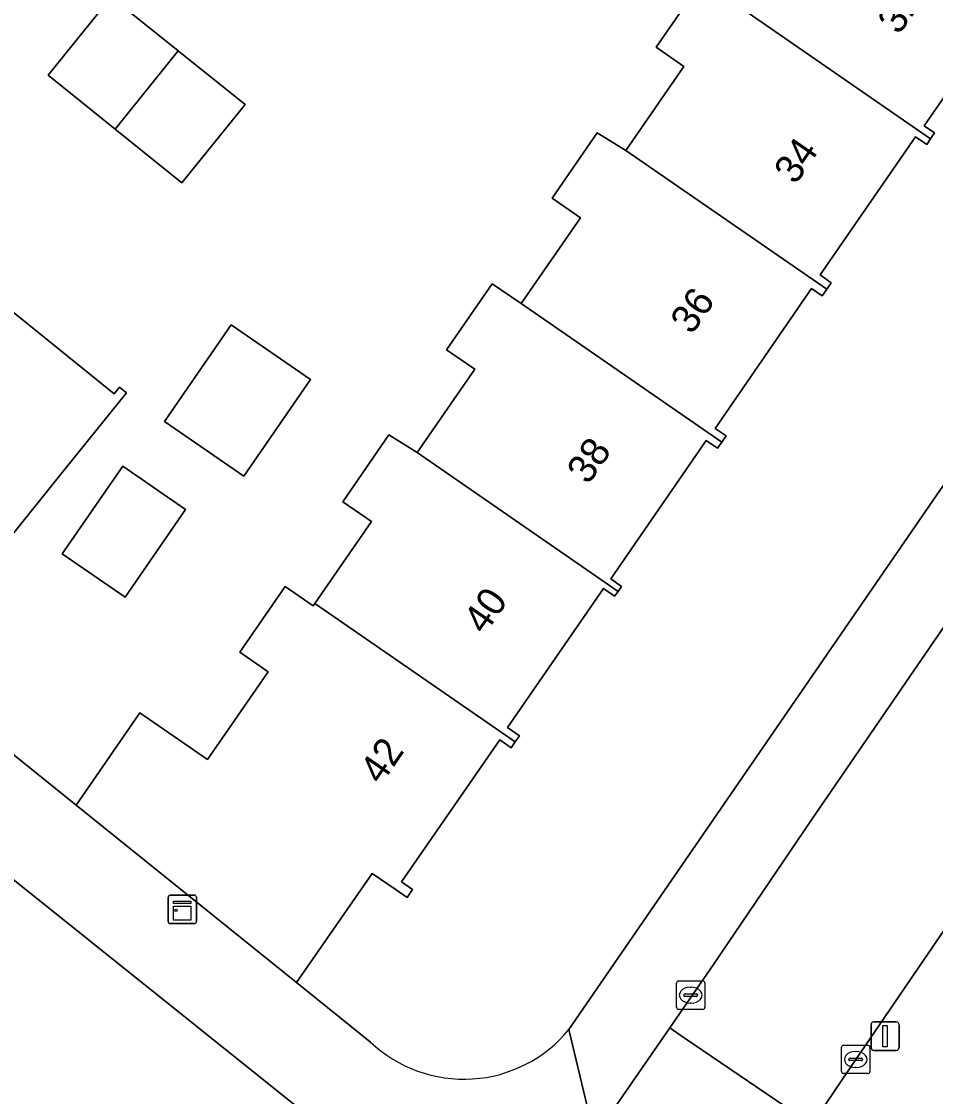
# Model space of a CAD drawing. Extents: x 160157 to 160921, y 381516 to 382045.
# Drawn here: x 160586.64 to 160618.81, y 381685.82 to 381723.64 of the extents above; entities that cross this region are included whole.
import ezdxf

# ---------------------------------------------------------------- set-up
doc = ezdxf.new("R2010")
doc.units = 0
for name, color, linetype in [('IMGEO_Erf', 7, 'Continuous'), ('IMGEO_Kast', 7, 'Continuous'), ('IMGEO_Kolk', 7, 'Continuous'), ('IMGEO_Lichtmast', 7, 'Continuous'), ('IMGEO_Pand', 7, 'Continuous'), ('IMGEO_Pand_nummerreeks', 7, 'Continuous'), ('IMGEO_Rijbaan_lokaal_open', 7, 'Continuous'), ('IMGEO_Voetpad_open', 7, 'Continuous')]:
    doc.layers.add(name, color=color, linetype=linetype)

msp = doc.modelspace()

# ---------------------------------------------------------------- linework, layer by layer
at = {"layer": 'IMGEO_Erf'}
for points in [[(160605.905, 381688.17), (160640.592, 381738.561)], [(160608.978, 381722.731), (160610.55, 381725.008)], [(160621.759, 381724.825), (160618.405, 381719.969), (160618.774, 381719.715), (160618.634, 381719.512), (160618.496, 381719.312), (160618.104, 381719.583), (160614.745, 381714.72), (160615.138, 381714.448), (160614.979, 381714.217), (160614.817, 381713.983), (160614.445, 381714.24), (160611.047, 381709.322), (160611.433, 381709.056), (160611.283, 381708.839), (160611.133, 381708.621), (160610.736, 381708.894), (160607.375, 381704.027), (160607.755, 381703.764), (160607.635, 381703.589), (160607.514, 381703.414), (160607.123, 381703.685), (160603.744, 381698.793), (160604.161, 381698.505), (160604.016, 381698.295), (160603.87, 381698.084), (160603.467, 381698.363), (160600.014, 381693.364), (160600.403, 381693.096), (160600.209, 381692.815), (160599.82, 381693.084), (160598.975, 381693.667), (160596.32, 381689.825), (160598.92, 381687.732)], [(160578.193, 381704.418), (160588.56, 381696.072), (160590.799, 381699.315), (160593.183, 381697.668), (160595.32, 381700.762), (160594.323, 381701.451), (160595.918, 381703.761), (160596.908, 381703.077), (160596.966, 381703.161), (160598.956, 381706.042), (160597.946, 381706.74), (160599.571, 381709.092), (160600.567, 381708.468), (160602.593, 381711.402), (160601.601, 381712.087), (160603.199, 381714.402), (160604.225, 381713.711), (160606.31, 381716.73), (160605.312, 381717.419), (160606.899, 381719.717), (160607.906, 381719.099), (160609.95, 381722.059), (160608.978, 381722.731)], [(160585.535, 381714.051), (160589.893, 381710.543), (160590.081, 381710.777), (160590.328, 381710.577), (160587.927, 381707.594), (160584.791, 381703.699)]]:
    msp.add_lwpolyline(points, dxfattribs=at)
for points in [[(160592.15, 381722.608), (160594.504, 381720.713), (160592.285, 381717.957), (160589.931, 381719.852), (160587.578, 381721.747), (160589.796, 381724.503)], [(160591.675, 381709.568), (160594.022, 381712.965), (160596.807, 381711.041), (160594.46, 381707.643)], [(160590.28, 381703.382), (160588.07, 381704.909), (160590.201, 381707.994), (160592.411, 381706.467)]]:
    msp.add_lwpolyline(points, close=True, dxfattribs=at)
msp.add_arc((160602.208, 381691.213), 4.788, 226.6311, 320.5451, dxfattribs=at)
at = {"layer": 'IMGEO_Kast'}
for p, q in [((160591.872, 381692.9), (160592.713, 381692.9)), ((160592.713, 381692.9), (160591.872, 381692.9)), ((160591.797, 381691.975), (160591.797, 381692.816)), ((160591.797, 381692.816), (160591.797, 381691.975)), ((160592.797, 381692.825), (160592.797, 381691.984)), ((160592.797, 381691.984), (160592.797, 381692.825)), ((160592.722, 381691.9), (160591.881, 381691.9)), ((160591.881, 381691.9), (160592.722, 381691.9))]:
    msp.add_line(p, q, dxfattribs=at)
for points in [[(160591.992, 381692.69), (160592.592, 381692.69), (160592.592, 381692.605), (160591.992, 381692.605), (160591.992, 381692.69)], [(160591.992, 381692.515), (160592.592, 381692.515), (160592.592, 381692.026), (160591.992, 381692.026), (160591.992, 381692.515)]]:
    msp.add_lwpolyline(points, dxfattribs=at)
msp.add_circle((160592.076, 381692.364), 0.0377, dxfattribs=at)
for centre, start, end in [((160591.875, 381692.822), 92.4484, 184.2845), ((160591.875, 381692.822), 92.4484, 184.2845), ((160592.719, 381692.822), 2.4484, 94.2845), ((160592.719, 381692.822), 2.4484, 94.2845), ((160591.875, 381691.978), 182.4484, 274.2845), ((160591.875, 381691.978), 182.4484, 274.2845), ((160592.719, 381691.978), 272.4484, 4.2845), ((160592.719, 381691.978), 272.4484, 4.2845)]:
    msp.add_arc(centre, 0.0779, start, end, dxfattribs=at)
at = {"layer": 'IMGEO_Kolk'}
for p, q in [((160609.69, 381688.957), (160609.69, 381689.809)), ((160609.765, 381689.883), (160610.617, 381689.883)), ((160610.691, 381689.809), (160610.691, 381688.957)), ((160609.992, 381689.426), (160610.39, 381689.426)), ((160610.178, 381689.663), (160610.203, 381689.663)), ((160609.949, 381689.377), (160609.949, 381689.389)), ((160610.387, 381689.34), (160609.989, 381689.34)), ((160610.201, 381689.103), (160610.176, 381689.103)), ((160610.433, 381689.389), (160610.433, 381689.377)), ((160610.617, 381688.883), (160609.765, 381688.883)), ((160615.498, 381686.695), (160615.498, 381687.547)), ((160615.573, 381687.621), (160616.425, 381687.621)), ((160616.499, 381687.547), (160616.499, 381686.695)), ((160615.8, 381687.164), (160616.198, 381687.164)), ((160615.986, 381687.401), (160616.011, 381687.401)), ((160615.757, 381687.115), (160615.757, 381687.127)), ((160616.195, 381687.078), (160615.797, 381687.078)), ((160616.009, 381686.841), (160615.984, 381686.841)), ((160616.241, 381687.127), (160616.241, 381687.115)), ((160616.425, 381686.621), (160615.573, 381686.621))]:
    msp.add_line(p, q, dxfattribs=at)
for points in [[(160609.69, 381688.957), (160609.69, 381689.809)], [(160609.765, 381689.883), (160610.617, 381689.883)], [(160610.691, 381689.809), (160610.691, 381688.957)], [(160610.617, 381688.883), (160609.765, 381688.883)], [(160615.498, 381686.695), (160615.498, 381687.547)], [(160615.573, 381687.621), (160616.425, 381687.621)], [(160616.499, 381687.547), (160616.499, 381686.695)], [(160616.425, 381686.621), (160615.573, 381686.621)]]:
    msp.add_lwpolyline(points, dxfattribs=at)
for centre, radius, start, end in [((160609.767, 381689.807), 0.0765, 91.552, 178.448), ((160609.767, 381689.807), 0.0765, 91.552, 178.448), ((160610.615, 381689.807), 0.0765, 1.552, 88.448), ((160610.615, 381689.807), 0.0765, 1.552, 88.448), ((160609.989, 381689.386), 0.0403, 85.8775, 175.7526), ((160610.394, 381689.388), 0.0386, 1.7309, 96.639), ((160609.986, 381689.376), 0.0366, 178.938, 274.7102), ((160610.39, 381689.383), 0.043, 264.8664, 352.4533), ((160609.767, 381688.959), 0.0765, 181.552, 268.448), ((160609.767, 381688.959), 0.0765, 181.552, 268.448), ((160610.615, 381688.959), 0.0765, 271.552, 358.448), ((160610.615, 381688.959), 0.0765, 271.552, 358.448), ((160615.575, 381687.545), 0.0765, 91.552, 178.448), ((160615.575, 381687.545), 0.0765, 91.552, 178.448), ((160616.423, 381687.545), 0.0765, 1.552, 88.448), ((160616.423, 381687.545), 0.0765, 1.552, 88.448), ((160615.797, 381687.124), 0.0403, 85.8775, 175.7526), ((160616.202, 381687.126), 0.0386, 1.7309, 96.639), ((160615.794, 381687.114), 0.0366, 178.938, 274.7102), ((160616.198, 381687.121), 0.043, 264.8664, 352.4533), ((160615.575, 381686.697), 0.0765, 181.552, 268.448), ((160615.575, 381686.697), 0.0765, 181.552, 268.448), ((160616.423, 381686.697), 0.0765, 271.552, 358.448), ((160616.423, 381686.697), 0.0765, 271.552, 358.448)]:
    msp.add_arc(centre, radius, start, end, dxfattribs=at)
for centre, major_axis, ratio, start_param, end_param in [((160610.177, 381689.383), (-0.387, 0.002), 0.722429, 4.712389, 7.853982), ((160610.202, 381689.383), (-0.39, 0.002), 0.717154, 1.570796, 4.712389), ((160615.985, 381687.121), (-0.387, 0.002), 0.722429, 4.712389, 7.853982), ((160616.01, 381687.121), (-0.39, 0.002), 0.717154, 1.570796, 4.712389)]:
    msp.add_ellipse(centre, major_axis=major_axis, ratio=ratio, start_param=start_param, end_param=end_param, dxfattribs=at)
at = {"layer": 'IMGEO_Lichtmast'}
for p, q in [((160616.537, 381687.541), (160616.537, 381688.341)), ((160616.537, 381688.341), (160616.537, 381687.541)), ((160616.637, 381688.441), (160617.427, 381688.441)), ((160617.427, 381688.441), (160616.637, 381688.441)), ((160617.527, 381688.341), (160617.527, 381687.541)), ((160617.527, 381687.541), (160617.527, 381688.341)), ((160617.427, 381687.441), (160616.637, 381687.441)), ((160616.637, 381687.441), (160617.427, 381687.441))]:
    msp.add_line(p, q, dxfattribs=at)
msp.add_lwpolyline([(160616.957, 381688.316), (160617.107, 381688.316), (160617.107, 381687.566), (160616.957, 381687.566), (160616.957, 381688.316)], dxfattribs=at)
for centre, start, end in [((160616.637, 381688.341), 90, 180), ((160616.637, 381688.341), 90, 180), ((160617.427, 381688.341), 0, 90), ((160617.427, 381688.341), 360, 90), ((160616.637, 381687.541), 180, 270), ((160616.637, 381687.541), 180, 270), ((160617.427, 381687.541), 270, 0), ((160617.427, 381687.541), 270, 0)]:
    msp.add_arc(centre, 0.1, start, end, dxfattribs=at)
at = {"layer": 'IMGEO_Pand'}
for points in [[(160618.634, 381719.512), (160618.774, 381719.715), (160618.405, 381719.969), (160621.759, 381724.825), (160622.167, 381724.544), (160622.316, 381724.76), (160614.228, 381730.33), (160612.619, 381728), (160613.595, 381727.326), (160611.566, 381724.39)], [(160618.634, 381719.512), (160611.566, 381724.39), (160610.55, 381725.008), (160608.978, 381722.731), (160609.95, 381722.059), (160607.906, 381719.099), (160614.979, 381714.217), (160615.138, 381714.448), (160614.745, 381714.72), (160618.104, 381719.583), (160618.496, 381719.312)], [(160592.15, 381722.608), (160589.796, 381724.503), (160587.578, 381721.747), (160589.931, 381719.852)], [(160592.15, 381722.608), (160589.931, 381719.852), (160592.285, 381717.957), (160594.504, 381720.713)], [(160604.225, 381713.711), (160611.283, 381708.839), (160611.433, 381709.056), (160611.047, 381709.322), (160614.445, 381714.24), (160614.817, 381713.983), (160614.979, 381714.217), (160607.906, 381719.099), (160606.899, 381719.717), (160605.312, 381717.419), (160606.31, 381716.73)], [(160585.548, 381714.52), (160579.982, 381707.608), (160580.186, 381707.444), (160580.444, 381707.765), (160584.753, 381704.296), (160584.477, 381703.952), (160584.791, 381703.699), (160587.927, 381707.594), (160590.328, 381710.577), (160590.081, 381710.777), (160589.893, 381710.543), (160585.535, 381714.051), (160585.769, 381714.342)], [(160604.225, 381713.711), (160603.199, 381714.402), (160601.601, 381712.087), (160602.593, 381711.402), (160600.567, 381708.468), (160607.635, 381703.589), (160607.755, 381703.764), (160607.375, 381704.027), (160610.736, 381708.894), (160611.133, 381708.621), (160611.283, 381708.839)], [(160591.675, 381709.568), (160594.46, 381707.643), (160596.807, 381711.041), (160594.022, 381712.965)], [(160604.016, 381698.295), (160604.161, 381698.505), (160603.744, 381698.793), (160607.123, 381703.685), (160607.514, 381703.414), (160607.635, 381703.589), (160600.567, 381708.468), (160599.571, 381709.092), (160597.946, 381706.74), (160598.956, 381706.042), (160596.966, 381703.161)], [(160590.28, 381703.382), (160592.411, 381706.467), (160590.201, 381707.994), (160588.07, 381704.909)], [(160604.016, 381698.295), (160596.966, 381703.161), (160596.908, 381703.077), (160595.918, 381703.761), (160594.323, 381701.451), (160595.32, 381700.762), (160593.183, 381697.668), (160590.799, 381699.315), (160588.56, 381696.072), (160596.32, 381689.825), (160598.975, 381693.667), (160599.82, 381693.084), (160600.209, 381692.815), (160600.403, 381693.096), (160600.014, 381693.364), (160603.467, 381698.363), (160603.87, 381698.084)]]:
    msp.add_lwpolyline(points, close=True, dxfattribs=at)
at = {"layer": 'IMGEO_Rijbaan_lokaal_open'}
for points in [[(160678.334, 381788.56), (160651.806, 381750), (160643.136, 381737.367), (160641.13, 381734.448), (160614.441, 381695.549), (160610.996, 381690.462), (160609.452, 381688.229), (160609.962, 381687.883), (160614.454, 381684.835), (160615.999, 381687.121), (160619.05, 381691.582), (160640.187, 381722.521), (160642.496, 381725.9), (160658.96, 381750), (160667.503, 381762.414)], [(160614.454, 381684.835), (160609.962, 381687.883), (160609.452, 381688.229), (160606.806, 381684.4)]]:
    msp.add_lwpolyline(points, dxfattribs=at)
msp.add_lwpolyline([(160568.758, 381707.591), (160557.554, 381716.59), (160557.502, 381716.634), (160557.472, 381716.661), (160550.945, 381722.011), (160550.931, 381722.022), (160550.918, 381722.034), (160550.145, 381722.678), (160546.247, 381717.93), (160547.02, 381717.298), (160547.066, 381717.257), (160553.47, 381712.091), (160558.948, 381707.655), (160565.145, 381702.637), (160577.959, 381692.258), (160593.928, 381679.339), (160594.486, 381678.894), (160598.404, 381683.766), (160597.642, 381684.404), (160592.745, 381688.322), (160581.553, 381697.274)], close=True, dxfattribs=at)
at = {"layer": 'IMGEO_Voetpad_open'}
msp.add_lwpolyline([(160707.501, 381830.956), (160711.08, 381836.076), (160711.248, 381836.325), (160707.078, 381835.076), (160693.176, 381814.897), (160692.079, 381813.304), (160675.928, 381789.86), (160675.328, 381788.989), (160648.467, 381750), (160641.671, 381740.128), (160640.592, 381738.561), (160605.905, 381688.17), (160606.806, 381684.4), (160609.452, 381688.229), (160610.996, 381690.462), (160614.441, 381695.549), (160641.13, 381734.448), (160643.136, 381737.367), (160651.806, 381750), (160678.334, 381788.56), (160680.332, 381791.464), (160692.328, 381808.901), (160699.651, 381819.545)], close=True, dxfattribs=at)
for points in [[(160716.089, 381833.009), (160716.028, 381832.837), (160712.504, 381827.801), (160703.573, 381814.824), (160700.524, 381810.394), (160670.296, 381766.471), (160667.503, 381762.414), (160658.96, 381750), (160642.496, 381725.9), (160640.187, 381722.521), (160619.05, 381691.582), (160615.999, 381687.121), (160614.454, 381684.835), (160611.203, 381680.025), (160615.694, 381677.246), (160615.835, 381678.381), (160616.408, 381679.37), (160644.455, 381719.97), (160645.316, 381721.217), (160665.2, 381750)], [(160557.472, 381716.661), (160557.502, 381716.634), (160557.554, 381716.59), (160568.758, 381707.591), (160581.553, 381697.274), (160592.745, 381688.322), (160597.642, 381684.404), (160598.404, 381683.766), (160598.577, 381683.621)], [(160598.92, 381687.732), (160596.32, 381689.825), (160588.56, 381696.072), (160578.193, 381704.418), (160572.841, 381708.802)], [(160606.806, 381684.4), (160605.905, 381688.17)]]:
    msp.add_lwpolyline(points, dxfattribs=at)
msp.add_arc((160602.208, 381691.213), 4.788, 226.6311, 320.5451, dxfattribs=at)

# ---------------------------------------------------------------- texts
at = {"layer": 'IMGEO_Pand_nummerreeks'}
for s, p in [('32', (160617.522, 381723.135)), ('34', (160613.877, 381717.862)), ('36', (160610.231, 381712.585)), ('38', (160606.587, 381707.311)), ('40', (160602.941, 381702.034)), ('42', (160599.292, 381696.753))]:
    msp.add_text(s, height=1, rotation=55.3565, dxfattribs=at).set_placement(p)

doc.saveas('drawing.dxf')
